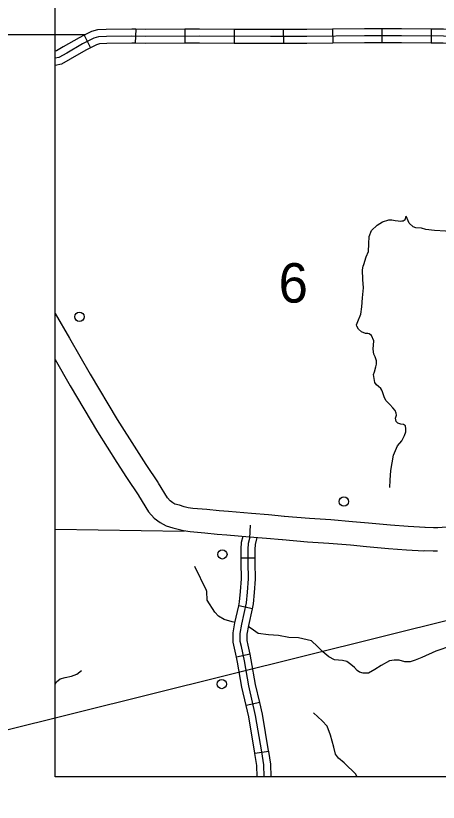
# Model space of a CAD drawing. Extents: x 1369979 to 1371646, y 379997 to 381064.
# Drawn here: x 1370539.6 to 1370592.6, y 380143.2 to 380241.9 of the extents above; entities that cross this region are included whole.
import ezdxf

# ---------------------------------------------------------------- set-up
doc = ezdxf.new("R2010")
doc.units = 0
for name, color, linetype in [('Default', 7, 'Continuous'), ('R_Border Notes', 7, 'Continuous'), ('R_No Plot', 7, 'Continuous')]:
    doc.layers.add(name, color=color, linetype=linetype)

msp = doc.modelspace()

# ---------------------------------------------------------------- linework, layer by layer
at = {"layer": 'Default'}
msp.add_line((1370501.904, 380143.18), (1370944.13, 380253.288), dxfattribs=at)
at = {"layer": 'R_Border Notes'}
for p, q in [((1370554.618, 380240.233), (1370554.564, 380238.476)), ((1370560.774, 380240.214), (1370560.781, 380238.456)), ((1370566.97, 380240.196), (1370566.96, 380238.438)), ((1370573.147, 380240.178), (1370573.157, 380238.42)), ((1370579.33, 380240.23), (1370579.349, 380238.472)), ((1370585.527, 380240.273), (1370585.527, 380238.515)), ((1370591.723, 380240.236), (1370591.706, 380238.478)), ((1370518.177, 380239.582), (1370544.495, 380239.582)), ((1370548.131, 380239.46), (1370548.929, 380237.894)), ((1370554.709, 380187.408), (1370554.7, 380187.421)), ((1370569.621, 380173.831), (1370567.863, 380173.803)), ((1370569.267, 380167.465), (1370567.551, 380167.842)), ((1370568.99, 380161.759), (1370567.269, 380161.4)), ((1370570.187, 380155.709), (1370568.474, 380155.315)), ((1370571.32, 380149.571), (1370569.586, 380149.287))]:
    msp.add_line(p, q, dxfattribs=at)
for points in [[(1370554.618, 380240.233), (1370554.144, 380240.247), (1370550.933, 380240.195), (1370549.807, 380240.137), (1370549.056, 380239.932), (1370548.131, 380239.46)], [(1370560.774, 380240.214), (1370555.833, 380240.195), (1370554.618, 380240.233)], [(1370566.97, 380240.196), (1370562.615, 380240.221), (1370560.774, 380240.214)], [(1370573.147, 380240.178), (1370571.533, 380240.169), (1370566.97, 380240.196)], [(1370579.33, 380240.23), (1370576.08, 380240.195), (1370573.147, 380240.178)], [(1370585.527, 380240.273), (1370583.343, 380240.273), (1370579.33, 380240.23)], [(1370591.723, 380240.236), (1370587.985, 380240.273), (1370585.527, 380240.273)], [(1370595.856, 380240.189), (1370593.247, 380240.221), (1370591.723, 380240.236)], [(1370544.495, 380239.582), (1370548.328, 380239.561)], [(1370548.131, 380239.46), (1370547.523, 380239.15), (1370545.532, 380237.997), (1370544.661, 380237.515), (1370544.495, 380237.477)], [(1370562.614, 380239.342), (1370555.821, 380239.316), (1370554.137, 380239.368), (1370550.962, 380239.316), (1370549.947, 380239.264), (1370549.375, 380239.108), (1370547.943, 380238.378), (1370545.966, 380237.232), (1370544.977, 380236.685), (1370544.495, 380236.576)], [(1370571.533, 380239.29), (1370562.614, 380239.342)], [(1370599.213, 380239.55), (1370598.495, 380239.42), (1370597.427, 380239.29), (1370593.237, 380239.342), (1370587.98, 380239.394), (1370583.348, 380239.394), (1370576.087, 380239.316), (1370571.533, 380239.29)], [(1370548.929, 380237.894), (1370548.364, 380237.606), (1370546.399, 380236.467), (1370545.292, 380235.855), (1370544.495, 380235.675)], [(1370554.564, 380238.476), (1370554.131, 380238.489), (1370550.992, 380238.437), (1370550.087, 380238.391), (1370549.693, 380238.283), (1370548.929, 380237.894)], [(1370560.781, 380238.456), (1370555.809, 380238.437), (1370554.564, 380238.476)], [(1370566.96, 380238.438), (1370562.613, 380238.463), (1370560.781, 380238.456)], [(1370573.157, 380238.42), (1370571.533, 380238.411), (1370566.96, 380238.438)], [(1370579.349, 380238.472), (1370576.094, 380238.437), (1370573.157, 380238.42)], [(1370585.527, 380238.515), (1370583.353, 380238.515), (1370579.349, 380238.472)], [(1370591.706, 380238.478), (1370587.976, 380238.515), (1370585.527, 380238.515)], [(1370595.834, 380238.431), (1370593.228, 380238.463), (1370591.706, 380238.478)], [(1370583.257, 380210.67), (1370583.562, 380211.64), (1370583.821, 380212.317), (1370583.864, 380213.268), (1370583.922, 380214.19), (1370584.238, 380214.94), (1370584.915, 380215.617), (1370585.606, 380216.064), (1370586.412, 380216.28), (1370586.787, 380216.309), (1370587.204, 380216.208), (1370587.578, 380216.15), (1370587.809, 380216.136), (1370588.01, 380216.15), (1370588.197, 380216.164), (1370588.428, 380216.323), (1370588.574, 380216.763)], [(1370592.136, 380214.968), (1370591.045, 380215.084), (1370590.498, 380215.257), (1370589.792, 380215.285), (1370589.461, 380215.43), (1370588.929, 380215.876), (1370588.574, 380216.763)], [(1370604.346, 380216.732), (1370603.048, 380216.381), (1370602.257, 380215.963), (1370601.522, 380215.718), (1370600.748, 380215.735), (1370599.928, 380215.591), (1370599.093, 380215.137), (1370598.265, 380214.943), (1370597.247, 380214.781), (1370595.606, 380214.738), (1370593.489, 380214.853), (1370592.136, 380214.968)], [(1370582.505, 380203.524), (1370582.879, 380204.452), (1370583.023, 380205.374), (1370583.095, 380206.498), (1370583.21, 380207.78), (1370583.124, 380208.818), (1370583.109, 380209.999), (1370583.167, 380210.489), (1370583.257, 380210.67)], [(1370544.495, 380204.518), (1370546.326, 380201.455), (1370548.913, 380196.913), (1370552.308, 380191.214), (1370554.709, 380187.408)], [(1370584.549, 380196.358), (1370584.463, 380196.881), (1370584.578, 380197.212), (1370584.751, 380197.832), (1370584.866, 380198.192), (1370584.837, 380198.61), (1370584.693, 380199.085), (1370584.506, 380199.446), (1370584.434, 380200.051), (1370584.506, 380201.103), (1370584.232, 380201.766), (1370583.916, 380201.982), (1370583.772, 380202.025), (1370583.484, 380202.011), (1370582.951, 380202.227), (1370582.591, 380202.558), (1370582.375, 380202.933), (1370582.346, 380203.135), (1370582.505, 380203.524)], [(1370544.495, 380198.749), (1370546.381, 380195.438), (1370549.81, 380189.683), (1370552.231, 380185.845)], [(1370588.479, 380190.43), (1370588.234, 380190.608), (1370587.889, 380190.637), (1370587.529, 380190.781), (1370587.328, 380190.997), (1370587.227, 380191.386), (1370587.342, 380191.775), (1370587.328, 380192.035), (1370587.198, 380192.366), (1370586.896, 380192.698), (1370586.507, 380193.116), (1370586.075, 380193.591), (1370585.859, 380193.966), (1370585.614, 380194.715), (1370585.528, 380194.917), (1370585.37, 380195.104), (1370585.096, 380195.363), (1370584.837, 380195.58), (1370584.621, 380195.868), (1370584.578, 380196.127), (1370584.549, 380196.358)], [(1370586.536, 380182.706), (1370586.579, 380183.599), (1370586.665, 380184.81), (1370586.982, 380186.77), (1370587.5, 380187.937), (1370588.019, 380188.571), (1370588.35, 380189.205), (1370588.522, 380189.666), (1370588.522, 380190.069), (1370588.479, 380190.43)], [(1370554.7, 380187.421), (1370555.893, 380185.574), (1370557.437, 380183.29)], [(1370552.239, 380185.832), (1370553.449, 380183.959), (1370555.01, 380181.649)], [(1370573.293, 380179.067), (1370571.293, 380179.255), (1370569.138, 380179.431), (1370566.287, 380179.677), (1370565.106, 380179.753), (1370563.56, 380179.912), (1370561.796, 380180.062), (1370561.201, 380180.158), (1370560.711, 380180.281), (1370560.115, 380180.457), (1370559.546, 380180.621), (1370559.274, 380180.769), (1370558.928, 380181.028), (1370558.596, 380181.395), (1370557.474, 380183.232)], [(1370554.973, 380181.706), (1370556.239, 380179.632), (1370556.947, 380178.851), (1370557.687, 380178.298), (1370558.426, 380177.895), (1370559.294, 380177.645), (1370559.938, 380177.454), (1370560.611, 380177.286), (1370561.439, 380177.152), (1370563.286, 380176.995), (1370564.862, 380176.833), (1370566.067, 380176.756), (1370568.893, 380176.512), (1370571.037, 380176.336), (1370573.019, 380176.15)], [(1370590.955, 380177.673), (1370588.835, 380177.803), (1370586.597, 380177.977), (1370583.86, 380178.214), (1370581.837, 380178.398), (1370579.096, 380178.625), (1370576.418, 380178.809), (1370573.276, 380179.068)], [(1370544.495, 380177.47), (1370560.718, 380177.223)], [(1370570.76, 380146.391), (1370570.709, 380147.864), (1370570.441, 380149.504), (1370569.663, 380154.068), (1370568.804, 380157.8), (1370568.268, 380160.915), (1370567.892, 380162.714), (1370567.731, 380163.372), (1370567.731, 380164.365), (1370567.946, 380165.546), (1370568.536, 380168.231), (1370568.643, 380169.574), (1370568.778, 380171.212), (1370568.751, 380173.279), (1370568.724, 380174.917), (1370568.777, 380175.687), (1370568.938, 380176.332), (1370569.015, 380177.971)], [(1370592.561, 380177.638), (1370592.005, 380177.645), (1370590.906, 380177.675)], [(1370595.57, 380177.839), (1370592.445, 380177.634)], [(1370567.863, 380173.803), (1370567.844, 380174.94), (1370567.906, 380175.825), (1370568.095, 380176.581)], [(1370569.621, 380173.831), (1370569.603, 380174.893), (1370569.649, 380175.549), (1370569.869, 380176.432)], [(1370573.035, 380176.149), (1370576.197, 380175.887), (1370578.875, 380175.704), (1370581.584, 380175.479), (1370583.601, 380175.296), (1370586.357, 380175.057), (1370588.632, 380174.88), (1370590.776, 380174.749)], [(1370592.521, 380174.708), (1370591.945, 380174.716), (1370590.825, 380174.747)], [(1370567.551, 380167.842), (1370567.665, 380168.361), (1370567.767, 380169.645), (1370567.898, 380171.242), (1370567.872, 380173.266), (1370567.863, 380173.803)], [(1370569.267, 380167.465), (1370569.407, 380168.101), (1370569.519, 380169.503), (1370569.657, 380171.181), (1370569.63, 380173.292), (1370569.621, 380173.831)], [(1370563.524, 380169.771), (1370562.056, 380172.768)], [(1370567.094, 380165.766), (1370566.72, 380165.823), (1370565.741, 380166.14), (1370565.021, 380166.543), (1370564.561, 380167.062), (1370563.61, 380168.532), (1370563.553, 380169.656), (1370563.524, 380169.771)], [(1370567.269, 380161.4), (1370567.035, 380162.52), (1370566.853, 380163.266), (1370566.853, 380164.444), (1370567.084, 380165.719), (1370567.551, 380167.842)], [(1370568.99, 380161.759), (1370568.75, 380162.908), (1370568.61, 380163.478), (1370568.61, 380164.286), (1370568.808, 380165.374), (1370569.267, 380167.465)], [(1370573.826, 380163.863), (1370572.536, 380164.123), (1370571.269, 380164.209), (1370569.973, 380164.353), (1370569.11, 380164.987), (1370568.78, 380165.218)], [(1370590.545, 380161.356), (1370589.69, 380161.01), (1370589.086, 380160.808), (1370588.423, 380160.808), (1370587.675, 380161.01), (1370587.07, 380161.039), (1370586.466, 380160.924), (1370585.429, 380160.347), (1370584.652, 380159.829), (1370583.845, 380159.396), (1370583.154, 380159.396), (1370582.723, 380159.512), (1370582.406, 380159.742), (1370582.089, 380160.088), (1370581.629, 380160.463), (1370581.11, 380160.866), (1370580.563, 380160.981), (1370580.074, 380161.039), (1370579.584, 380161.068), (1370578.864, 380161.442), (1370578.116, 380162.048), (1370577.425, 380162.739), (1370576.705, 380163.46), (1370575.035, 380163.806), (1370573.826, 380163.863)], [(1370607.619, 380160.448), (1370606.842, 380161.327), (1370606.324, 380161.788), (1370605.316, 380162.019), (1370605.028, 380162.047), (1370604.596, 380161.99), (1370604.279, 380161.846), (1370603.847, 380161.529), (1370603.732, 380161.068), (1370603.358, 380160.808), (1370602.753, 380160.866), (1370602.264, 380160.895), (1370601.746, 380161.212), (1370601.083, 380161.817), (1370600.536, 380162.22), (1370599.874, 380162.422), (1370599.269, 380162.336), (1370598.406, 380162.307), (1370597.398, 380162.566), (1370596.477, 380162.797), (1370595.008, 380162.854), (1370594.26, 380162.825), (1370592.302, 380162.134), (1370590.545, 380161.356)], [(1370570.187, 380155.709), (1370569.666, 380157.974), (1370569.131, 380161.079), (1370568.99, 380161.759)], [(1370568.474, 380155.315), (1370567.942, 380157.627), (1370567.404, 380160.751), (1370567.269, 380161.4)], [(1370544.495, 380158.016), (1370544.663, 380158.287), (1370545.124, 380158.661), (1370545.786, 380158.849), (1370546.549, 380159.022), (1370547.225, 380159.252), (1370547.83, 380159.728)], [(1370569.586, 380149.287), (1370569.574, 380149.359), (1370568.801, 380153.896), (1370568.474, 380155.315)], [(1370571.32, 380149.571), (1370571.307, 380149.649), (1370570.525, 380154.241), (1370570.187, 380155.709)], [(1370579.471, 380150.112), (1370579.085, 380151.585), (1370578.639, 380152.752), (1370578.02, 380153.415), (1370576.94, 380154.424)], [(1370582.421, 380146.391), (1370582.192, 380146.755), (1370581.803, 380147.159), (1370581.285, 380147.648), (1370580.767, 380148.138), (1370580.076, 380148.715), (1370579.716, 380149.233), (1370579.471, 380150.112)], [(1370569.88, 380146.391), (1370569.832, 380147.777), (1370569.586, 380149.287)], [(1370571.639, 380146.391), (1370571.585, 380147.95), (1370571.32, 380149.571)]]:
    msp.add_lwpolyline(points, dxfattribs=at)
for centre in [(1370547.55, 380204.121), (1370580.754, 380180.929), (1370565.498, 380174.303), (1370565.429, 380158.025)]:
    msp.add_circle(centre, 0.586, dxfattribs=at)
at = {"layer": 'R_No Plot'}
msp.add_lwpolyline([(1370544.495, 380586.867), (1371140.383, 380586.867), (1371140.383, 380146.391), (1370544.495, 380146.391)], close=True, dxfattribs=at)

# ---------------------------------------------------------------- texts
at = {"layer": 'R_Border Notes'}
msp.add_text('6', height=4.95, dxfattribs=at).set_placement((1370572.558, 380205.905))

doc.saveas('drawing.dxf')
